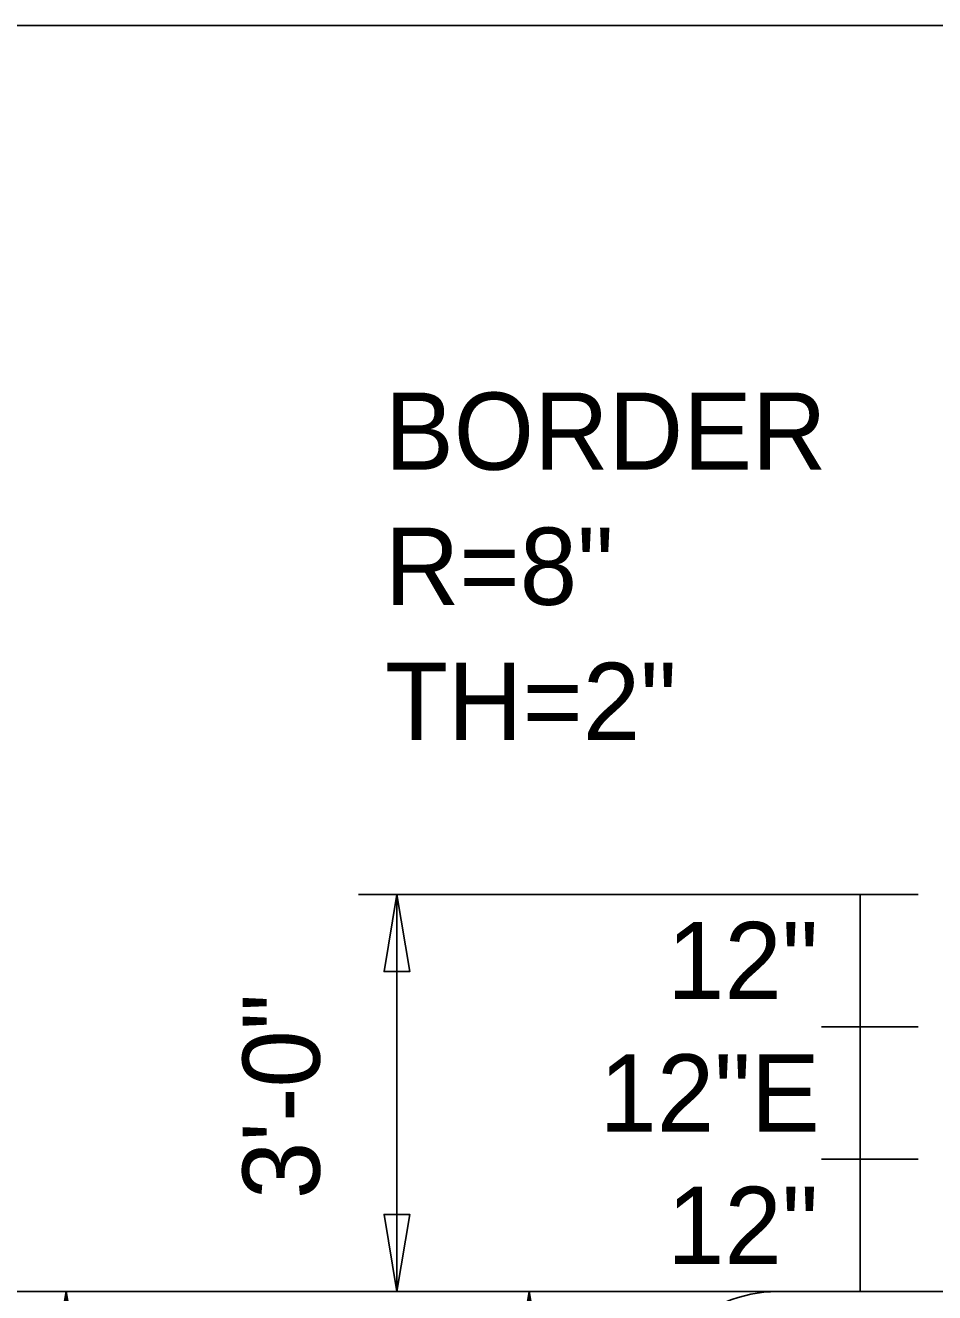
# Model space of a CAD drawing. Extents: x 2149934 to 2150188, y 145113 to 145238.
# Drawn here: x 2150026.84 to 2150033.71, y 145157.37 to 145166.95 of the extents above; entities that cross this region are included whole.
import ezdxf

# ---------------------------------------------------------------- set-up
doc = ezdxf.new("R2010")
doc.units = 0
for name, color, linetype in [('GSBWFILL', 7, 'Continuous'), ('GSCOLORFILL', 7, 'Continuous'), ('GSDIMS', 7, 'Continuous'), ('GSOUTLINE', 7, 'Continuous'), ('Level 1', 7, 'Continuous')]:
    doc.layers.add(name, color=color, linetype=linetype)

msp = doc.modelspace()

# ---------------------------------------------------------------- linework, layer by layer
at = {"layer": 'GSBWFILL'}
msp.add_line((2150046.0199, 145157.3826), (2150032.5199, 145157.3826), dxfattribs=at)
msp.add_arc((2150032.5199, 145156.3826), 1, 90, 180, dxfattribs=at)
at = {"layer": 'GSCOLORFILL'}
msp.add_line((2150046.0199, 145157.3826), (2150032.5199, 145157.3826), dxfattribs=at)
msp.add_line((2150046.0199, 145157.3826), (2150032.5199, 145157.3826), dxfattribs=at)
msp.add_line((2150046.0199, 145157.3826), (2150032.5199, 145157.3826), dxfattribs=at)
msp.add_arc((2150032.5199, 145156.3826), 1, 90, 180, dxfattribs=at)
msp.add_arc((2150032.5199, 145156.3826), 1, 90, 180, dxfattribs=at)
msp.add_arc((2150032.5199, 145156.3826), 1, 90, 180, dxfattribs=at)
at = {"layer": 'GSDIMS'}
for p, q in [((2150030.0819, 145160.3837), (2150029.3527, 145160.3837)), ((2150029.6444, 145157.3826), (2150029.6444, 145160.3837)), ((2150033.5819, 145160.3837), (2150030.0819, 145160.3837)), ((2150033.5819, 145160.3837), (2150032.8527, 145160.3837)), ((2150033.1444, 145159.3832), (2150033.1444, 145160.3837)), ((2150033.5819, 145159.3832), (2150032.8527, 145159.3832)), ((2150033.5819, 145159.3832), (2150032.8527, 145159.3832)), ((2150033.1444, 145159.3832), (2150033.1444, 145158.3832)), ((2150033.5819, 145158.3832), (2150032.8527, 145158.3832)), ((2150033.5819, 145158.3832), (2150032.8527, 145158.3832)), ((2150033.1444, 145157.3826), (2150033.1444, 145158.3832)), ((2150031.0823, 145157.3827), (2150024.0823, 145157.3827)), ((2150027.5823, 145157.3827), (2150026.8531, 145157.3827)), ((2150027.1448, 145155.8352), (2150027.1448, 145157.3827)), ((2150030.0819, 145157.3826), (2150029.3527, 145157.3826)), ((2150033.5819, 145157.3826), (2150030.0819, 145157.3826)), ((2150031.0823, 145157.3827), (2150030.3531, 145157.3827)), ((2150030.6448, 145156.0601), (2150030.6448, 145157.3827)), ((2150033.5819, 145157.3826), (2150032.8527, 145157.3826))]:
    msp.add_line(p, q, dxfattribs=at)
for points in [[(2150029.6444, 145160.3837), (2150029.7416, 145159.8004), (2150029.5472, 145159.8004)], [(2150029.6444, 145157.3826), (2150029.7416, 145157.9659), (2150029.5472, 145157.9659)], [(2150027.1448, 145157.3827), (2150027.242, 145156.7994), (2150027.0476, 145156.7994)], [(2150030.6448, 145157.3827), (2150030.742, 145156.7994), (2150030.5476, 145156.7994)]]:
    msp.add_lwpolyline(points, close=True, dxfattribs=at)
at = {"layer": 'GSOUTLINE'}
msp.add_line((2150046.0199, 145157.3826), (2150032.5199, 145157.3826), dxfattribs=at)
msp.add_arc((2150032.5199, 145156.3826), 1, 90, 180, dxfattribs=at)
at = {"layer": 'Level 1'}
msp.add_line((2150135.4472, 145166.9499), (2150017.5574, 145166.9499), dxfattribs=at)

# ---------------------------------------------------------------- texts
at = {"layer": 'GSDIMS'}
for s, p in [('BORDER', (2150029.5533, 145163.5921)), ('R=8"', (2150029.5533, 145162.5713)), ('TH=2"', (2150029.5533, 145161.5504)), ('12"', (2150031.685, 145159.5918)), ('12"E', (2150031.1744, 145158.5916)), ('12"', (2150031.685, 145157.5913))]:
    msp.add_text(s, height=0.58333, dxfattribs=at).set_placement(p)
msp.add_text('3\'-0"', height=0.58333, rotation=90, dxfattribs=at).set_placement((2150029.061, 145158.0813))

doc.saveas('drawing.dxf')
